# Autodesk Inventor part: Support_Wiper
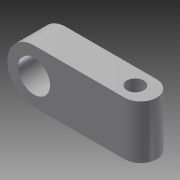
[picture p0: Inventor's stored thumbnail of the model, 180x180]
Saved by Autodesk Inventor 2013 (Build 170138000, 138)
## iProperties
Created: 2006-03
Part Number: Support_Wiper
Document SubType Name: Modeling
Designer: debonom
Material: Stainless Steel, 440C
Mass: 138.885 g
Surface Area: 61.269 cm^2
Volume: 17.9206 cm^3
Density: 7.75 g/cm^3
Author: debonom
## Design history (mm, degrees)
sketch "Sketch1"
  geometry: L1 (-37.5, 0)-(50, 0) reference; L2 (25, 12.5)-(-25, 12.5); L3 (-25, 12.5)-(-25, -12.5); L4 (-25, -12.5)-(25, -12.5); L5 (25, -12.5)-(25, 12.5); L6 (25, 12.5)-(-25, -12.5); A1 r 12.5 centre (25, 0) between (25, -12.5) and (25, 12.5); 1 further point
  constraints: 10 end point, 2 midpoint, 2 parallel, 2 point on circle, 1 centre point, 1 horizontal, 1 perpendicular, 1 point on line
  dimensions: "d11" = 25 distance of L4.end L2.start; "d12" = 50 distance of L2.start L2.end
extrude "Extrusion1" new body sketch "Sketch1" stored distance "d3" = 15; taper "d4" = 0 deg
sketch "Sketch4"
  geometry: C1 r 7.5 at (25, 0); A1 r 12.5 centre (25, 0) between (25, -12.5) and (25, 12.5) reference; 1 further point
  constraints: 1 centre point, 1 coincident
  dimensions: "d13" = 15 diameter of C1
extrude "Extrusion3" cut sketch "Sketch4" stored distance "d14" = 15; taper "d15" = 0 deg
sketch "Sketch3"
  geometry: L1 (-5, 0)-(30, 0) reference; L2 (25, -7.5)-(25, 7.5) reference; C1 r 4 at (15, 0); 1 further point
  constraints: 1 centre point, 1 point on line
  dimensions: "d8" = 8 diameter of C1; "d16" = 10 distance from line of L2 C1.centre
extrude "Extrusion2" cut sketch "Sketch3" stored distance "d9" = 15; taper "d10" = 0 deg
fillet "Fillet2"
body "Solid1"
